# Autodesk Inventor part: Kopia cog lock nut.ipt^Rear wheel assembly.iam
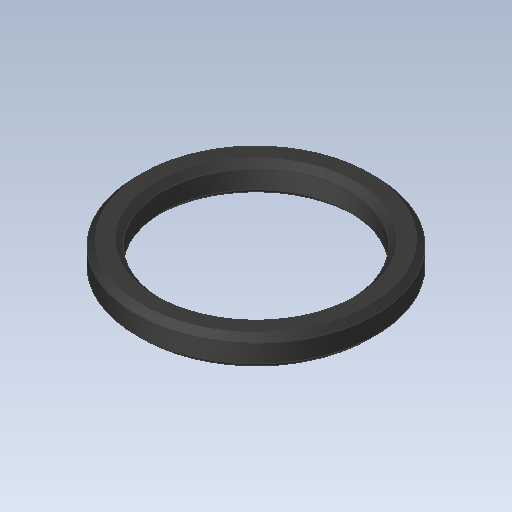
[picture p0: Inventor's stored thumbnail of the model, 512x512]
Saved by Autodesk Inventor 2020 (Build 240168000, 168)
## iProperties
Created: 2017-09
Part Number: Kopia cog lock nut.ipt^Rear wheel assembly.iam
Material: Ogólny
Document SubType Name: Modeling
Designer: Tomasz
Density: 1 g/cm^3
Appearance: Domyślna
Sending System: SolidWorks 2017
Last Author: Tomasz
Last Saved: 2017-09-11
Author: Tomasz
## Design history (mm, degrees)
feature "cog lock nut.ipt"
node "Bryła1"
